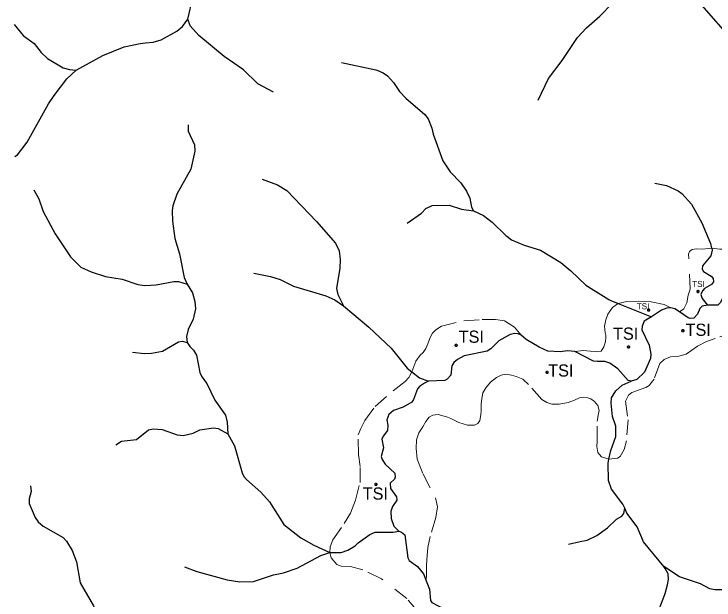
# Model space of a CAD drawing. Extents: x 473.9 to 500, y 7733.1 to 7760.8.
# Drawn here: x 476.883 to 481.483, y 7751.231 to 7755.079 of the extents above; entities that cross this region are included whole.
import ezdxf
from ezdxf.enums import TextEntityAlignment as Align

# ---------------------------------------------------------------- set-up
doc = ezdxf.new("R2010")
doc.units = 0
doc.header["$LTSCALE"] = 0.032
doc.header["$PDMODE"] = 32
doc.header["$PDSIZE"] = 0.016
doc.linetypes.add('SHORT_DASHED', pattern=[2.7, 1.5, -1.2])
doc.layers.add('21', color=7, linetype='SHORT_DASHED', lineweight=13)
doc.layers.add('7', color=7, linetype='Continuous', lineweight=25)
doc.layers.add('61', color=7, linetype='Continuous')

msp = doc.modelspace()

# ---------------------------------------------------------------- linework, layer by layer
at = {"layer": '21'}
for points in [[(481.4679, 7753.5409), (481.4695, 7753.541), (481.5223, 7753.5349), (481.5625, 7753.534), (481.6176, 7753.53), (481.6486, 7753.53), (481.6591, 7753.5322), (481.6678, 7753.5357), (481.6765, 7753.5418), (481.6888, 7753.5558), (481.7093, 7753.5816), (481.7246, 7753.6148), (481.7743, 7753.7148), (481.8134, 7753.8118), (481.8236, 7753.8595), (481.827, 7753.9293), (481.8219, 7754.0059), (481.8015, 7754.0945), (481.7794, 7754.2494), (481.7487, 7754.4265), (481.7572, 7754.5031), (481.7794, 7754.5695), (481.8015, 7754.6155), (481.8339, 7754.6566)], [(481.2559, 7753.1228), (481.2839, 7753.1427), (481.3043, 7753.1836), (481.3139, 7753.2323), (481.3263, 7753.2718), (481.3163, 7753.5028), (481.3225, 7753.5188), (481.3401, 7753.5326), (481.3656, 7753.5377), (481.4065, 7753.536), (481.4679, 7753.5409)], [(480.5693, 7752.8638), (480.625, 7752.8703), (480.669, 7752.8645), (480.7101, 7752.8624), (480.7411, 7752.866), (480.7582, 7752.893), (480.7673, 7752.9188), (480.7704, 7752.9315), (480.7722, 7752.9529), (480.7713, 7752.9695), (480.7695, 7752.9782), (480.7673, 7752.9848), (480.7646, 7753.0286), (480.7731, 7753.0712), (480.785, 7753.1086), (480.8157, 7753.1529), (480.8535, 7753.1776)], [(480.8535, 7753.1776), (480.911, 7753.1904), (480.9876, 7753.1938), (481.0711, 7753.1887), (481.1562, 7753.1716), (481.1995, 7753.1487)], [(479.498, 7752.7292), (479.5234, 7752.7988), (479.5523, 7752.8396), (479.5711, 7752.8567), (479.5898, 7752.8822), (479.6017, 7752.9128), (479.6153, 7752.9503), (479.6341, 7752.9827), (479.6545, 7753.0048), (479.692, 7753.0303), (479.8401, 7753.0644), (479.9593, 7753.0729), (480.0478, 7753.0729), (480.1057, 7753.0644), (480.1721, 7753.0235), (480.2167, 7752.9708)], [(481.6148, 7752.994), (481.4906, 7752.9475), (481.4339, 7752.9294), (481.3738, 7752.8971), (481.3009, 7752.8454), (481.2522, 7752.8327), (481.1964, 7752.827), (481.1559, 7752.8103), (481.1272, 7752.7832), (481.0901, 7752.6822), (481.079, 7752.6676), (481.0582, 7752.6403), (481.0361, 7752.6262), (480.9428, 7752.5927), (480.9205, 7752.577), (480.9027, 7752.5377), (480.9186, 7752.4147), (480.9083, 7752.277), (480.8936, 7752.2196), (480.8676, 7752.1741), (480.848, 7752.162), (480.7931, 7752.1553)], [(478.9586, 7751.5429), (478.9615, 7751.5797), (478.9786, 7751.6257), (479.0535, 7751.7329), (479.0943, 7751.801), (479.1267, 7751.8862), (479.1573, 7752.0019), (479.159, 7752.1075), (479.1482, 7752.1874), (479.1454, 7752.3161), (479.1624, 7752.3578), (479.188, 7752.4106), (479.2561, 7752.5008), (479.3753, 7752.6047), (479.4536, 7752.666), (479.4774, 7752.6932), (479.498, 7752.7292)], [(480.7931, 7752.1553), (480.7442, 7752.1705), (480.7203, 7752.1994), (480.7135, 7752.2386), (480.7152, 7752.2727), (480.7145, 7752.4063), (480.7237, 7752.4553), (480.7276, 7752.4747), (480.7203, 7752.5093), (480.6982, 7752.5349), (480.6744, 7752.5519), (480.6539, 7752.5587), (480.6267, 7752.5621), (480.5994, 7752.5587), (480.5671, 7752.5434), (480.5245, 7752.5281), (480.4666, 7752.5161), (480.4173, 7752.5178), (480.3849, 7752.5281), (480.3526, 7752.5485), (480.264, 7752.6472), (480.2266, 7752.6813), (480.184, 7752.6983), (480.1517, 7752.7085), (480.1125, 7752.7136), (480.0853, 7752.7085), (480.0529, 7752.6915), (480.0137, 7752.6609), (479.9848, 7752.6251), (479.9644, 7752.5911), (479.9576, 7752.5536), (479.9542, 7752.5178), (479.9525, 7752.4736), (479.9508, 7752.4463), (479.9439, 7752.4106), (479.9303, 7752.3901), (479.9099, 7752.3799), (479.8639, 7752.3782), (479.806, 7752.397), (479.7532, 7752.4225), (479.7311, 7752.4327), (479.6954, 7752.4429), (479.6698, 7752.4497), (479.6358, 7752.4446), (479.6119, 7752.4327), (479.5898, 7752.4038), (479.5694, 7752.368), (479.5438, 7752.3288), (479.5285, 7752.2829), (479.5251, 7752.225), (479.5336, 7752.1552), (479.5711, 7752.0564), (479.6528, 7751.9015), (479.6664, 7751.8419), (479.6562, 7751.7721), (479.6187, 7751.6478), (479.6017, 7751.5763), (479.5952, 7751.4945), (479.593, 7751.4585), (479.5949, 7751.3975), (479.5925, 7751.3562)], [(479.5388, 7751.1545), (479.4658, 7751.2416), (479.2978, 7751.3703), (479.1767, 7751.43), (479.0942, 7751.4522), (479.0336, 7751.4539), (479.0041, 7751.4639), (478.9683, 7751.5082), (478.9586, 7751.5429)]]:
    msp.add_lwpolyline(points, dxfattribs=at)
for p in [(481.3781, 7753.2567), (481.0533, 7753.1354), (481.2785, 7752.999), (479.7889, 7752.9038), (480.9213, 7752.8929), (480.3865, 7752.7262), (479.2615, 7751.9906)]:
    msp.add_point(p, dxfattribs=at)
at = {"layer": '7'}
msp.add_line((480.8535, 7753.1776), (481.0718, 7753.0901), dxfattribs=at)
for points in [[(478.025, 7755.0459), (478.0584, 7755.1873), (478.0481, 7755.2753), (478.0516, 7755.3173), (478.0633, 7755.457), (478.1515, 7755.6754), (478.1675, 7755.7473), (478.1698, 7755.8469), (478.1817, 7755.8887), (478.2229, 7755.9816), (478.2438, 7756.0779), (478.2905, 7756.2049), (478.3061, 7756.2336), (478.3391, 7756.278), (478.4058, 7756.3374), (478.4234, 7756.3617), (478.4445, 7756.4557), (478.511, 7756.5046), (478.5642, 7756.5797)], [(480.3268, 7754.5144), (480.3955, 7754.6558), (480.4854, 7754.773), (480.5862, 7754.9244), (480.6452, 7754.9881), (480.733, 7755.064), (480.815, 7755.1485), (480.9701, 7755.2753), (481.0187, 7755.3592), (481.0626, 7755.3936)], [(481.2873, 7755.3318), (481.3035, 7755.284), (481.3429, 7755.2123), (481.3853, 7755.1545), (481.6194, 7754.8875), (481.6812, 7754.7882), (481.7064, 7754.7588), (481.7416, 7754.726), (481.8047, 7754.6895), (481.8339, 7754.6566)], [(477.2918, 7754.7109), (477.4665, 7754.8058), (477.607, 7754.8645), (477.713, 7754.8845), (477.747, 7754.8909), (477.7983, 7754.8946), (477.8514, 7754.9092), (477.9543, 7754.9659), (477.9917, 7754.9966), (478.025, 7755.0459)], [(478.5877, 7754.5651), (478.4865, 7754.6214), (478.3907, 7754.7127), (478.2648, 7754.8009), (478.0972, 7754.9372), (478.0405, 7755.0015), (478.025, 7755.0459)], [(476.8834, 7755.0109), (476.9426, 7754.9373), (477.0153, 7754.8853), (477.0614, 7754.8273), (477.1029, 7754.7876), (477.2075, 7754.7261), (477.2481, 7754.7143), (477.2918, 7754.7109)], [(479.0358, 7754.7615), (479.2608, 7754.713), (479.2738, 7754.7076), (479.3092, 7754.6929), (479.3379, 7754.6722), (479.3781, 7754.6293), (479.4174, 7754.5692), (479.4573, 7754.5255), (479.5832, 7754.419), (479.6043, 7754.3906), (479.6297, 7754.3303), (479.6379, 7754.2899), (479.7023, 7754.1143), (479.7488, 7754.0424), (479.8185, 7753.9711), (479.8576, 7753.916), (479.8782, 7753.8689), (479.8891, 7753.8098), (479.9039, 7753.7872)], [(476.8883, 7754.144), (476.9055, 7754.1551), (476.9695, 7754.2385), (477.1093, 7754.4895), (477.1472, 7754.5448), (477.2316, 7754.6542), (477.2918, 7754.7109)], [(478.0279, 7754.352), (478.0274, 7754.3104), (478.0698, 7754.2204), (478.0721, 7754.1774), (478.0454, 7754.0613), (477.9528, 7753.897), (477.927, 7753.8185), (477.9237, 7753.7895), (477.9254, 7753.718), (477.941, 7753.6054), (477.9719, 7753.5051), (478.0008, 7753.348), (478.0203, 7753.3051)], [(478.5135, 7753.9942), (478.6152, 7753.9567), (478.6762, 7753.9196), (478.872, 7753.7174), (478.9958, 7753.5733), (479.0191, 7753.5244), (479.0271, 7753.466), (479.0254, 7753.4105), (479.0029, 7753.2761), (479.0122, 7753.238), (479.0488, 7753.1621)], [(481.0949, 7753.9675), (481.172, 7753.9527), (481.248, 7753.9183), (481.2724, 7753.9011), (481.3353, 7753.831), (481.4026, 7753.7078), (481.4591, 7753.5721), (481.4678, 7753.5414), (481.4679, 7753.5409)], [(477.0145, 7753.9253), (477.0465, 7753.8662), (477.0756, 7753.7827), (477.154, 7753.6353), (477.2541, 7753.4841), (477.323, 7753.4169), (477.3897, 7753.3857), (477.484, 7753.3561), (477.5947, 7753.338), (477.6978, 7753.3031), (477.7436, 7753.297), (477.8168, 7753.3006), (477.9329, 7753.3227), (477.9645, 7753.3217), (478.0203, 7753.3051)], [(479.4674, 7753.7058), (479.5608, 7753.7707), (479.59, 7753.802), (479.6321, 7753.8214), (479.7425, 7753.8229), (479.8234, 7753.7975), (479.9039, 7753.7872)], [(479.9039, 7753.7872), (479.9677, 7753.7552), (480.0262, 7753.7115), (480.115, 7753.6249), (480.1228, 7753.6193), (480.1536, 7753.5973), (480.2366, 7753.561), (480.3422, 7753.5286), (480.4756, 7753.4476), (480.543, 7753.3926), (480.642, 7753.2991), (480.7919, 7753.2051), (480.8046, 7753.1972), (480.8535, 7753.1776)], [(481.4679, 7753.5409), (481.4716, 7753.5279), (481.4622, 7753.492), (481.4066, 7753.4253), (481.4052, 7753.404), (481.414, 7753.3891), (481.4639, 7753.3568), (481.4769, 7753.3422), (481.4796, 7753.3198), (481.4667, 7753.3021), (481.4197, 7753.2756), (481.4067, 7753.2616), (481.3974, 7753.2369), (481.4044, 7753.2108), (481.4409, 7753.1674)], [(481.746, 7753.4764), (481.7407, 7753.4658), (481.7054, 7753.4592), (481.6865, 7753.466), (481.6725, 7753.471), (481.6436, 7753.4739), (481.6173, 7753.466), (481.5815, 7753.44), (481.5557, 7753.3713), (481.5433, 7753.219), (481.5233, 7753.1829), (481.5076, 7753.1672), (481.4409, 7753.1674)], [(478.4596, 7753.3782), (478.5695, 7753.3565), (478.6325, 7753.3355), (478.7202, 7753.2922), (478.9327, 7753.2295), (478.9911, 7753.2018), (479.0488, 7753.1621)], [(478.0203, 7753.3051), (478.0559, 7753.2492), (478.072, 7753.1918), (478.0753, 7753.1427), (478.0599, 7753.0755), (478.0271, 7753.0077), (478.0168, 7752.9609), (478.0212, 7752.9216)], [(479.0488, 7753.1621), (479.1154, 7753.1059), (479.2141, 7753.0226), (479.3624, 7752.8838), (479.4667, 7752.7532), (479.498, 7752.7292)], [(481.4409, 7753.1674), (481.4046, 7753.1611), (481.3892, 7753.1462), (481.3752, 7753.1073), (481.3513, 7753.0827), (481.327, 7753.0796), (481.3129, 7753.0847), (481.2559, 7753.1228)], [(481.1995, 7753.1487), (481.1729, 7753.1483), (481.1373, 7753.1342), (481.0718, 7753.0901)], [(481.2559, 7753.1228), (481.225, 7753.1434), (481.1995, 7753.1487)], [(481.0718, 7753.0901), (481.0252, 7753.0613), (481.0108, 7753.0286), (481.0094, 7753.0045), (481.0571, 7752.9039), (481.0677, 7752.8449), (481.0658, 7752.8176), (481.027, 7752.7281), (480.9761, 7752.6801), (480.9382, 7752.6686)], [(480.2167, 7752.9708), (480.1965, 7752.9793), (480.1739, 7752.9804), (480.1436, 7752.9752), (480.0701, 7752.9325), (480.0158, 7752.88), (479.993, 7752.8662), (479.8407, 7752.8352), (479.7987, 7752.8111), (479.7744, 7752.7913), (479.7606, 7752.7684), (479.7528, 7752.7069), (479.7308, 7752.6807), (479.715, 7752.6733), (479.6076, 7752.6679)], [(480.5693, 7752.8638), (480.5194, 7752.8674), (480.4721, 7752.8598), (480.3919, 7752.8654), (480.3333, 7752.8913), (480.2498, 7752.9414), (480.2167, 7752.9708)], [(477.6617, 7752.8585), (477.7393, 7752.8497), (477.7861, 7752.8513), (477.8583, 7752.8646), (477.9641, 7752.9266), (477.9895, 7752.9314), (478.0212, 7752.9216)], [(478.0212, 7752.9216), (478.0385, 7752.8954), (478.064, 7752.8728), (478.0828, 7752.8394), (478.1046, 7752.7258), (478.1149, 7752.7002), (478.1352, 7752.6735), (478.1516, 7752.652), (478.2031, 7752.544), (478.2724, 7752.4458), (478.2844, 7752.3982), (478.2887, 7752.323)], [(480.9382, 7752.6686), (480.9181, 7752.6731), (480.8511, 7752.7486), (480.798, 7752.7867), (480.7651, 7752.7965), (480.7164, 7752.7983), (480.6917, 7752.7992), (480.5693, 7752.8638)], [(479.498, 7752.7292), (479.5485, 7752.6904), (479.6076, 7752.6679)], [(479.6076, 7752.6679), (479.5817, 7752.6554), (479.5477, 7752.6336), (479.535, 7752.6172), (479.5093, 7752.547), (479.4968, 7752.5301), (479.4407, 7752.4978), (479.3768, 7752.476), (479.3475, 7752.4493), (479.3333, 7752.4142), (479.3408, 7752.3787), (479.3377, 7752.345), (479.3088, 7752.3076), (479.3004, 7752.2875), (479.3114, 7752.2295), (479.2971, 7752.1725), (479.3018, 7752.1535), (479.3231, 7752.1236), (479.3853, 7752.063), (479.3885, 7752.0386), (479.3839, 7752.0237), (479.3545, 7751.999), (479.3577, 7751.9642), (479.3965, 7751.909), (479.3996, 7751.8876), (479.3714, 7751.8462), (479.3598, 7751.8122), (479.3608, 7751.7674), (479.3786, 7751.7165), (479.4111, 7751.6824)], [(480.7931, 7752.1553), (480.8048, 7752.2135), (480.8391, 7752.3046), (480.8375, 7752.3729), (480.8167, 7752.4359), (480.8073, 7752.5248), (480.8103, 7752.5579), (480.8383, 7752.6046), (480.88, 7752.6426), (480.9382, 7752.6686)], [(477.5522, 7752.2512), (477.5908, 7752.2733), (477.6892, 7752.285), (477.7673, 7752.3476), (477.8004, 7752.3543), (477.8561, 7752.3501), (477.9561, 7752.3164), (477.9954, 7752.3109), (478.0607, 7752.3263), (478.1056, 7752.3478), (478.1951, 7752.3621), (478.2246, 7752.3563), (478.2887, 7752.323)], [(478.2887, 7752.323), (478.3317, 7752.2433), (478.3822, 7752.0657), (478.3946, 7752.0428), (478.411, 7752.0216), (478.5064, 7751.9398), (478.5626, 7751.8765), (478.6564, 7751.7274), (478.7678, 7751.6399), (478.8539, 7751.5907), (478.9586, 7751.5429)], [(480.8967, 7751.834), (480.8847, 7751.8614), (480.8087, 7751.9594), (480.7894, 7752.0157), (480.7878, 7752.1287), (480.7931, 7752.1553)], [(476.9923, 7751.981), (476.9953, 7751.9431), (476.9825, 7751.8958), (476.9825, 7751.8658), (477.0216, 7751.7739), (477.0416, 7751.745), (477.0753, 7751.7155), (477.2056, 7751.6411), (477.2294, 7751.6186), (477.2658, 7751.5552), (477.2936, 7751.4814), (477.3192, 7751.3449), (477.4052, 7751.1928), (477.4526, 7751.0769), (477.4887, 7750.9644), (477.5043, 7750.9412)], [(480.5263, 7751.5973), (480.6044, 7751.6145), (480.6492, 7751.6244), (480.7126, 7751.6543), (480.7826, 7751.7057), (480.8433, 7751.7628), (480.8779, 7751.7827), (480.8903, 7751.7992), (480.8967, 7751.834)], [(481.1528, 7751.4504), (481.0192, 7751.6123), (480.9785, 7751.7111), (480.9114, 7751.8006), (480.8967, 7751.834)], [(478.9586, 7751.5429), (479.0322, 7751.5436), (479.0761, 7751.5576), (479.1255, 7751.5862), (479.146, 7751.6075), (479.1916, 7751.64), (479.2225, 7751.662), (479.2566, 7751.6759), (479.375, 7751.6759), (479.4111, 7751.6824)], [(479.4111, 7751.6824), (479.4307, 7751.6767), (479.4508, 7751.6583), (479.4705, 7751.5074), (479.4811, 7751.4896), (479.535, 7751.4516), (479.5751, 7751.4033), (479.5925, 7751.3562)], [(478.0044, 7751.4498), (478.085, 7751.4174), (478.2847, 7751.3642), (478.3674, 7751.3503), (478.458, 7751.3537), (478.5892, 7751.3975), (478.6541, 7751.4106), (478.7451, 7751.4407), (478.9, 7751.5241), (478.9586, 7751.5429)], [(480.9886, 7750.7029), (480.996, 7750.7656), (481.0276, 7750.8166), (481.042, 7750.8524), (481.0625, 7750.9788), (481.0884, 7751.0822), (481.1481, 7751.2388), (481.1617, 7751.2744), (481.1776, 7751.3301), (481.1839, 7751.3658), (481.1822, 7751.4037), (481.1624, 7751.4388), (481.1528, 7751.4504)], [(481.5737, 7751.298), (481.4886, 7751.2985), (481.4551, 7751.3053), (481.3948, 7751.3377), (481.2571, 7751.3837), (481.1528, 7751.4504)], [(479.5925, 7751.3562), (479.6127, 7751.3014), (479.6201, 7751.2279), (479.6296, 7751.214), (479.7113, 7751.1714), (479.7359, 7751.1459), (479.7324, 7751.1289), (479.6997, 7751.0988), (479.6902, 7751.0729), (479.7116, 7751.0091), (479.7131, 7750.9872), (479.6922, 7750.9661), (479.6391, 7750.9408), (479.6249, 7750.9186), (479.6216, 7750.8784), (479.6572, 7750.7901), (479.6564, 7750.765), (479.6435, 7750.7266), (479.6248, 7750.7064)]]:
    msp.add_lwpolyline(points, dxfattribs=at)

# ---------------------------------------------------------------- texts
at = {"layer": '61'}
for height, p in [(0.04, (481.3815, 7753.2865)), (0.04, (481.017, 7753.1403)), (0.08, (480.9025, 7752.9403)), (0.08, (481.3792, 7752.9657)), (0.08, (479.8883, 7752.9203)), (0.08, (480.4765, 7752.6983)), (0.08, (479.2575, 7751.8901))]:
    msp.add_text('TSI', height=height, dxfattribs=at).set_placement(p, align=Align.CENTER)

doc.saveas('drawing.dxf')
